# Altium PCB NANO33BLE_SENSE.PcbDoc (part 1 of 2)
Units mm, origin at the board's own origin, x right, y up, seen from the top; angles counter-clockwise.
Board outline 43.18 x 17.78 mm, 4 copper layers (TOP, GND, SIG, BOTTOM), stack 1.586 mm thick; 73 components, 66 nets, 343 pads, 193 vias.
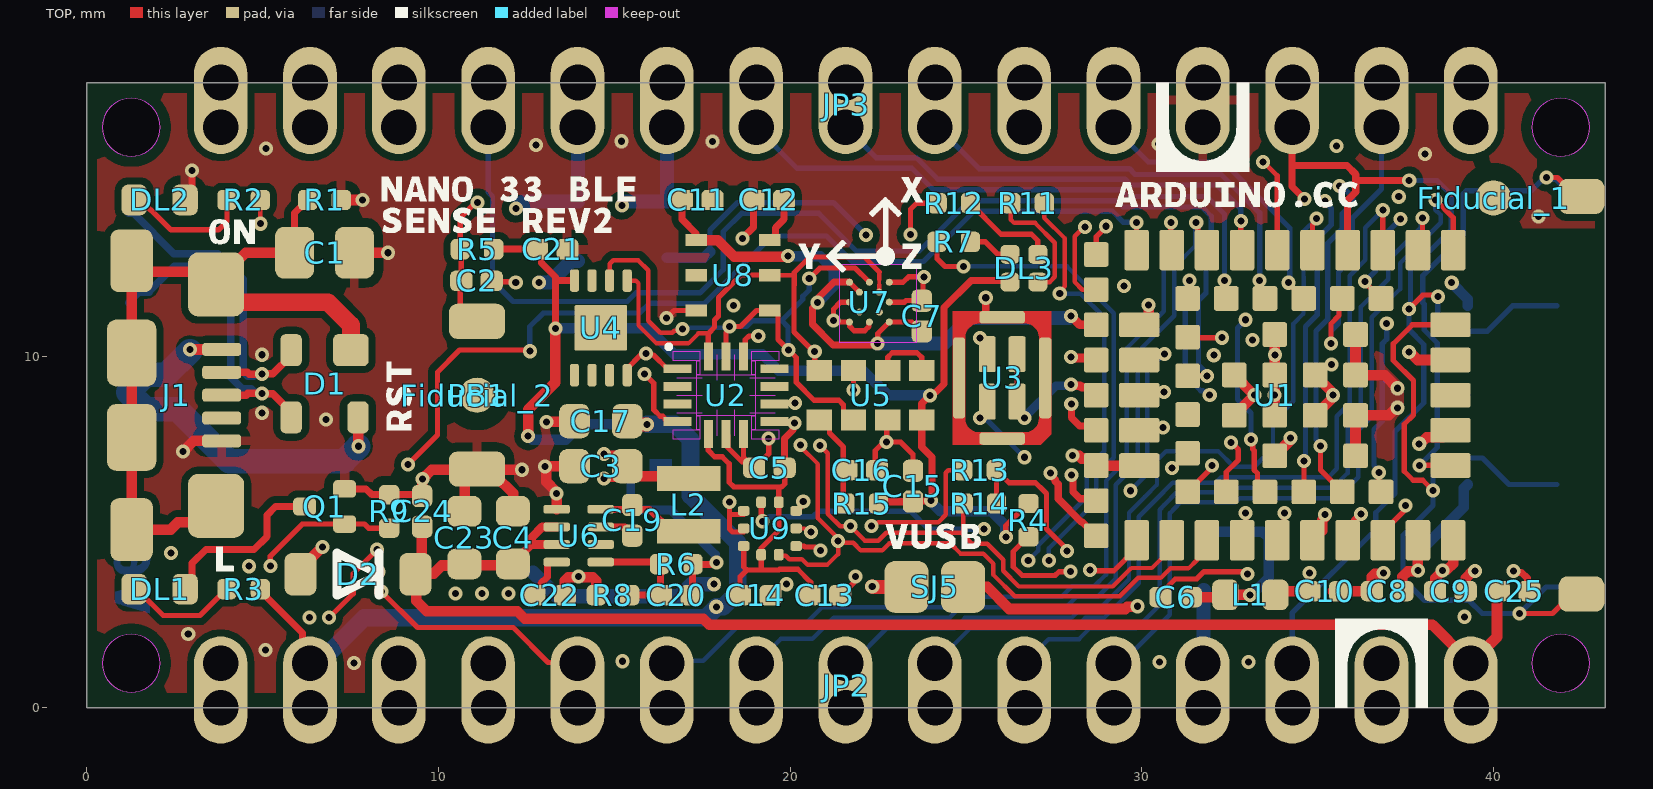
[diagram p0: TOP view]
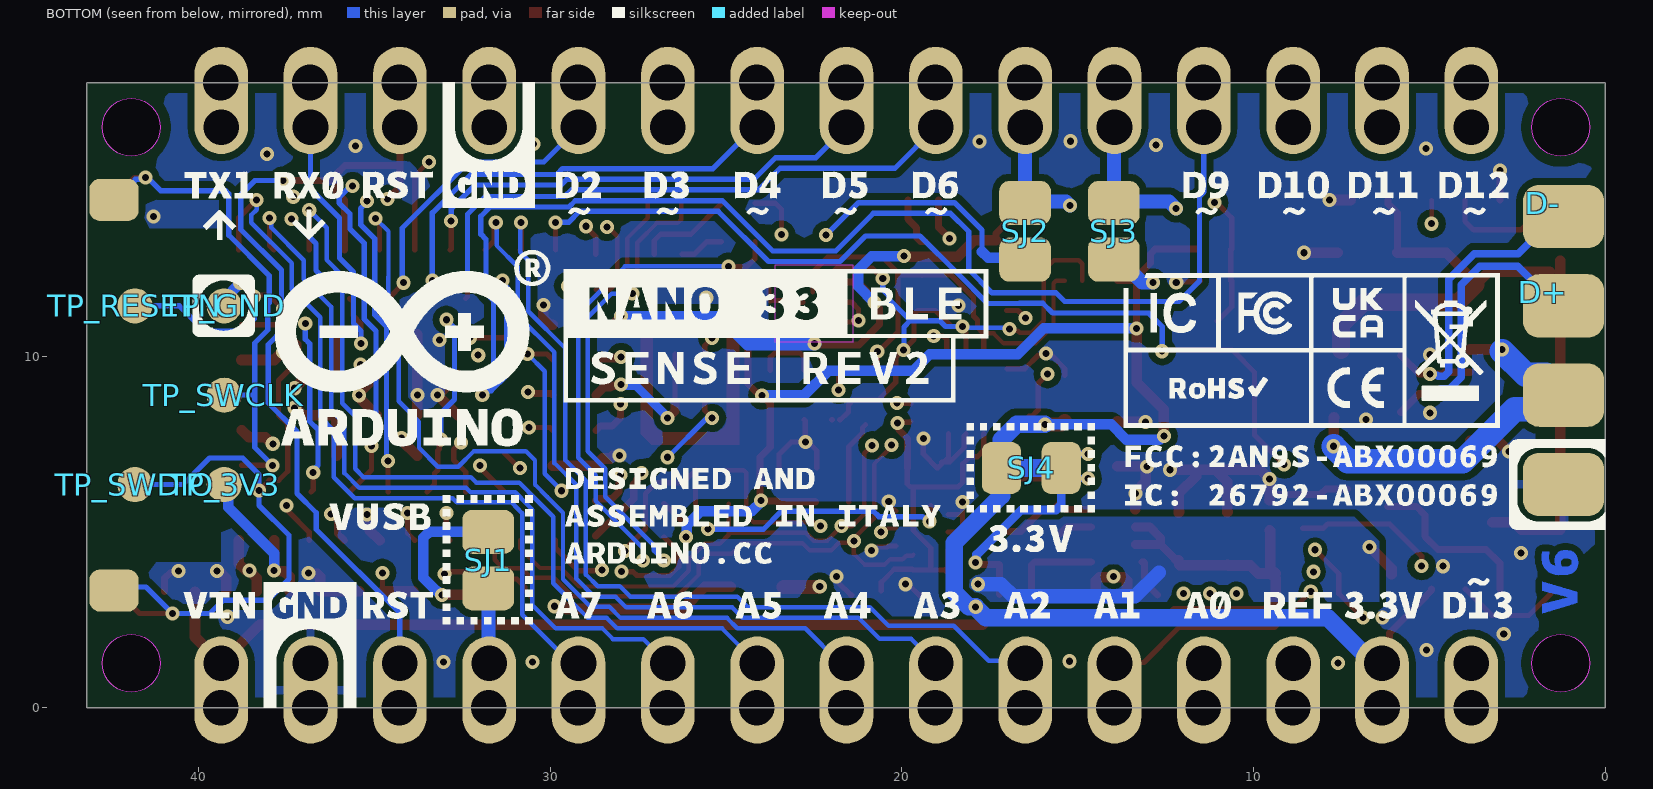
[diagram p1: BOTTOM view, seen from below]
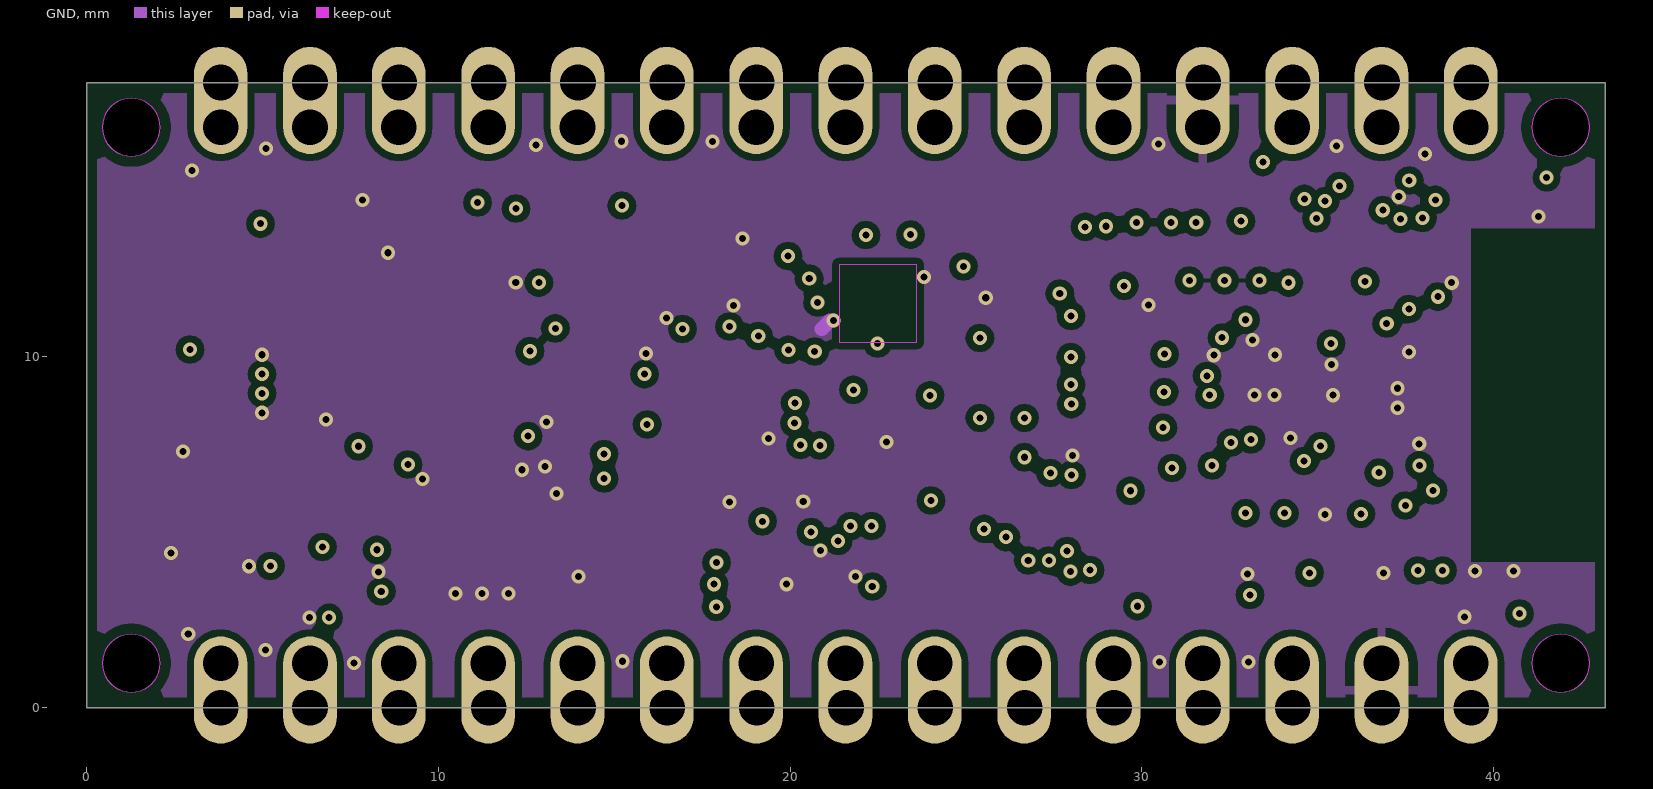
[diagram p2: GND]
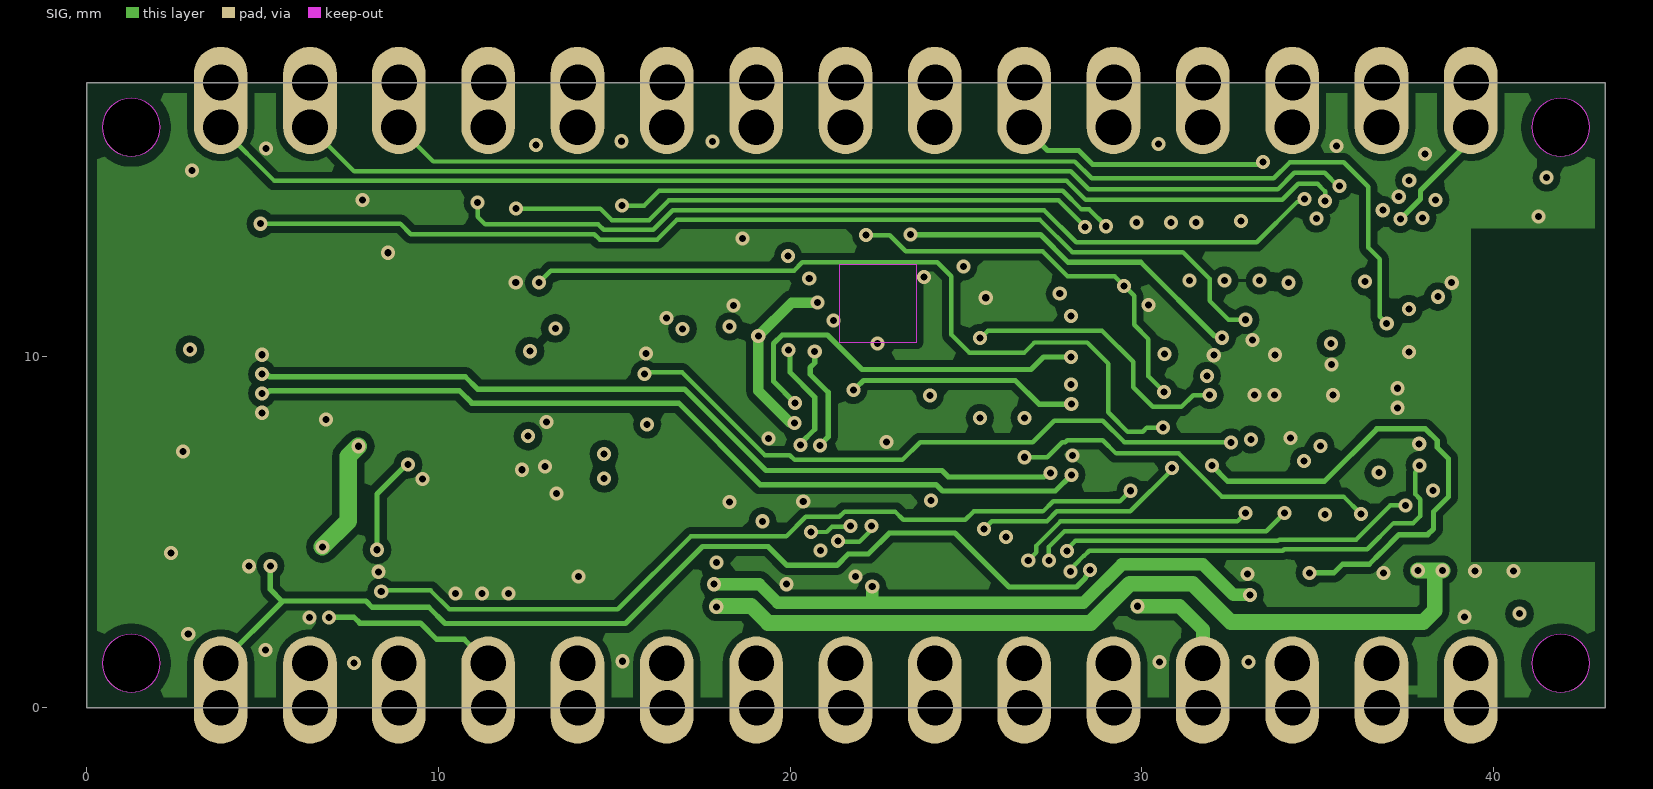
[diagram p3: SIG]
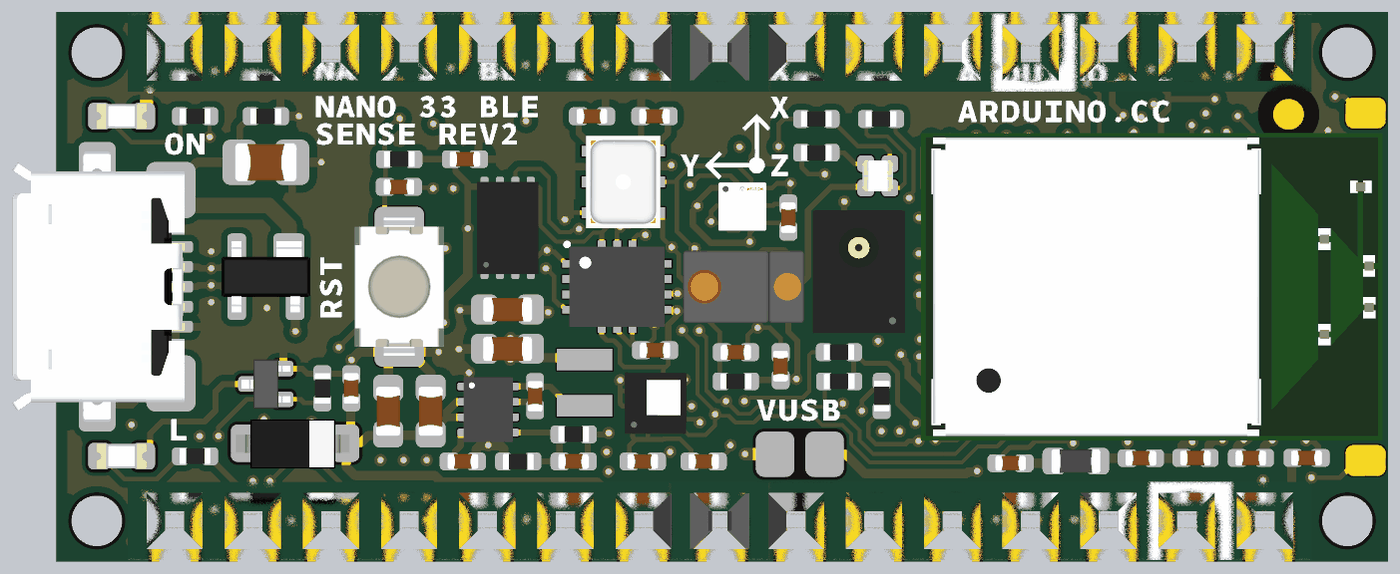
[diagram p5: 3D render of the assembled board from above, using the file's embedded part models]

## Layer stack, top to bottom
Top Solder: solder mask 0.0102, Solder Resist, Dk 3.5
TOP: signal copper 0.018
Dielectric 1: prepreg 0.14, PP-014, Dk 4.2
GND: signal copper 0.035
Dielectric2: core 1.2, FR-4, Dk 4.8
SIG: signal copper 0.035
Dielectric3: prepreg 0.14, PP-014, Dk 4.2
BOTTOM: signal copper 0.018
Bottom Solder: solder mask 0.0102, Solder Resist, Dk 3.5

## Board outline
43.18,0 0,0 0,17.78 43.18,17.78
cut-out: 1.27,0.445 ccw(c1.27,1.27) 2.095,1.27 ccw(c1.27,1.27) 1.27,2.095 ccw(c1.27,1.27) 0.445,1.27 ccw(c1.27,1.27)
cut-out: 1.27,15.684 ccw(c1.27,16.51) 2.095,16.51 ccw(c1.27,16.51) 1.27,17.335 ccw(c1.27,16.51) 0.445,16.51 ccw(c1.27,16.51)
cut-out: 41.91,15.684 ccw(c41.91,16.51) 42.735,16.51 ccw(c41.91,16.51) 41.91,17.335 ccw(c41.91,16.51) 41.084,16.51 ccw(c41.91,16.51)
cut-out: 41.91,0.445 ccw(c41.91,1.27) 42.735,1.27 ccw(c41.91,1.27) 41.91,2.095 ccw(c41.91,1.27) 41.084,1.27 ccw(c41.91,1.27)

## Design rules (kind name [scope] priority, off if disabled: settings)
BoardOutlineClearance USBbottomPADS [(ObjectKind = 'Pad') And (Component = 'Free') And (AsMM(PadXSize_AllLayers) = 2.3) And (AsMM(PadYSize_AllLayers) = 1.8)] p1: gap=0 ignorepadtopadclearanceinfootprint=FALSE
BoardOutlineClearance swdio_swclk [(ObjectKind = 'Pad') And (Name = 'Free-JTAG_PAD')] p2: gap=0 ignorepadtopadclearanceinfootprint=FALSE
BoardOutlineClearance Silk [(OnLayer('Top Overlay') OR OnLayer('Bottom Overlay'))] p3: gap=0 ignorepadtopadclearanceinfootprint=FALSE
BoardOutlineClearance MountingHoles [(ObjectKind = 'Pad') And (Name = 'Free-MH')] p4: gap=0 ignorepadtopadclearanceinfootprint=FALSE
BoardOutlineClearance Header_Castellated [((ObjectKind = 'Pad') And (Component = 'JP2')) OR                                                                                    ((ObjectKind = 'Pad') And (Component = 'JP3'))] p5: gap=0 ignorepadtopadclearanceinfootprint=FALSE
BoardOutlineClearance [All] p6: gap=0.3 ignorepadtopadclearanceinfootprint=FALSE
Clearance BGAclearance [WithinRoom('BGAfanout')] p1: gap=0.108 ignorepadtopadclearanceinfootprint=TRUE
Clearance GND_POLYGONS [(InNamedPolygon('GND_TOP') OR InNamedPolygon('GND_2') OR InNamedPolygon('GND_3') OR InNamedPolygon('GND_BOT'))] p2: gap=0.2 ignorepadtopadclearanceinfootprint=FALSE
Clearance "Generic clearance 0.15mm" [All] p3: gap=0.15 ignorepadtopadclearanceinfootprint=FALSE
ComponentClearance [All] p1: gap=0 collisioncheckmode=3 verticalgap=0 showdistances=FALSE
DiffPairsRouting [InDifferentialPairClass('USB')] p1: maxlimit=0.254 minlimit=0.15 mostfreqgap=0.254 toplayer_maxgap=0.15 toplayer_prefgap=0.15 toplayer_minwidth=0.21 toplayer_maxwidth=0.21 toplayer_prefwidth=0.21 midlayer14_mingap=0.25 midlayer14_maxgap=0.25 midlayer14_prefgap=0.25 midlayer14_minwidth=0.15 midlayer14_maxwidth=0.15 midlayer14_prefwidth=0.15 bottomlayer_maxgap=0.15 bottomlayer_prefgap=0.15 bottomlayer_minwidth=0.21 bottomlayer_maxwidth=0.21 bottomlayer_prefwidth=0.21 impedanceprofiledriven=TRUE impedanceprofileid={9B09AC36-4A16-4C97-8BAC-77357264EF75} impedanceprofilevalue=90.000000 maxuncoupledlength=12.7
HoleSize [All] p1: absolutevalues=TRUE maxlimit=6 minlimit=0.2 maxpercent=80.000 minpercent=20.000
HoleToHoleClearance [All] p1: gap=0.25 allowstackedmicrovias=TRUE
MinimumAnnularRing [All] p1: minimumring=0.1
MinimumSolderMaskSliver MinimumSolderMaskSliver_1 [(ObjectKind = 'Pad') And (Component = 'Fiducial_1') And (Name = 'Fiducial_1-1')] p1: minsoldermaskwidth=-1
MinimumSolderMaskSliver [All] p2: minsoldermaskwidth=0.147
NetAntennae Inductor [(ObjectKind = 'Component') And (Comment = 'MAKK2016T3R3M')] p1: netantennaetolerance=10
NetAntennae [All] p2: netantennaetolerance=0
PolygonConnect [All] p1: thpad.connectstyle=Relief thpad.reliefconductorwidth=0.254 thpad.reliefentries=4 thpad.polygonreliefangle="90 Angle" thpad.airgapwidth=0.254 smdpad.connectstyle=Relief smdpad.reliefconductorwidth=0.254 smdpad.reliefentries=4 smdpad.polygonreliefangle="90 Angle" smdpad.airgapwidth=0.254 via.connectstyle=Direct via.reliefconductorwidth=0.254 via.reliefentries=4 via.polygonreliefangle="90 Angle" via.airgapwidth=0.254
RoomDefinition BGAfanout [False vs False] p1: confinementstyle=ConfineIn formatcopy=TRUE lockcomponents=FALSE outline 22.16,12.23 22.925,12.23 22.925,11.702 22.16,11.702
RoomDefinition NANO33BLE_SENSE [InComponentClass('NANO33BLE_SENSE')] p2: confinementstyle=ConfineIn formatcopy=TRUE lockcomponents=FALSE outline 0,0 43.18,0 43.18,17.78 0,17.78
RoutingVias [All] p1: holewidth=0.2 width=0.4 viastyle="Through Hole" minholewidth=0.2 minwidth=0.4 maxholewidth=0.2 maxwidth=0.4
ShortCircuit SJ4 [Component = 'SJ4' vs (InNet('+3V3') OR InNet('NetC3_2'))] p1: allowed=TRUE
ShortCircuit [All] p2: allowed=FALSE
SilkToSilkClearance [All] p1: silktosilkclearance=0.2
SilkToSolderMaskClearance [IsPad] p1: minsilkscreentomaskgap=0 clearancetoexposedcopper=TRUE
SolderMaskExpansion Solder_VIA [IsVia] p1: expansion=0.102 istentingtop=TRUE
SolderMaskExpansion [All] p2: expansion=0.102 istentingtop=FALSE
UnRoutedNet [All] p1: checkbadconnections=TRUE
Width BGAwidth [WithinRoom('BGAfanout')] p1: maxlimit=3 minlimit=0.108 preferedwidth=0.15 midlayer1_minwidth=0.127 midlayer14_minwidth=0.127 bottomlayer_minwidth=0.127 minimp=50.000000 maximp=50.000000 favimp=50.000000
Width [All] p2: maxlimit=5 minlimit=0.127 preferedwidth=0.2 minimp=50.000000 maximp=50.000000 favimp=50.000000
20 further rules are at their usual default settings.

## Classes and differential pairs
differential pair class USB: USB
pad class SMDPaste_OFF: FD1-P$1 J3-4
differential pair USB: +USB_P -USB_N

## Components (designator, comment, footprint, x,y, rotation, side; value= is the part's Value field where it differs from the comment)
C1 "C0805C472KDRACTU" CAP-0805 6.765,12.94 r180 top value=4.7nF
C2 "GRM155R61H104KE19D" CAP-0402 11.085,12.14 r0 top value=100nF
C3 "GRM188R61E106MA73J" CAP-0603 14.62,6.87 r0 top value=10µF
C4 "GRM188R61E106MA73J" CAP-0603 12.12,4.84 r270 top value=10µF
C5 "C0402C104K4RACTU" CAP-0402 19.412,6.825 r180 top value=100nF
C6 "C0402C100K5RACTU" CAP-0402 30.965,3.148 r180 top value=1nF
C7 "GRM155R61H104KE19D" CAP-0402 23.745,11.14 r270 top value=100nF
C8 "GRM155R61H104KE19D" CAP-0402 36.975,3.32 r0 top value=100nF
C9 "GRM155R61H104KE19D" CAP-0402 38.775,3.32 r0 top value=100nF
C10 "C0402C100K5RACTU" CAP-0402 35.2,3.312 r0 top value=1nF
C11 "GRM155R61H104KE19D" CAP-0402 17.362,14.44 r0 top value=100nF
C12 "GRM155R61H104KE19D" CAP-0402 19.392,14.44 r180 top value=100nF
C13 "C0402C103K5RACTU" CAP-0402 20.991,3.205 r0 top value=10nF
C14 "GRM155R60J475ME47D" CAP-0402 19.012,3.205 r0 top value=4.7µF
C15 "C0402C105K8PACTU" CAP-0402 23.494,6.305 r270 top value=1µF
C16 "C0402C105K8PACTU" CAP-0402 22.038,6.76 r180 top value=1µF
C17 "GRM188R61E106MA73J" CAP-0603 14.62,8.15 r0 top value=10µF
C19 "GRM155R61H104KE19D" CAP-0402 15.515,5.33 r270 top value=100nF
C20 "C0402C220J5GAC7411" CAP-0402 16.765,3.205 r0 top value=22pF
C21 "GRM155R61H104KE19D" CAP-0402 13.235,13.04 r180 top value=100nF
C22 "C0402C105K8PACTU" CAP-0402 13.165,3.205 r180 top value=1µF
C23 "GRM188R61E106MA73J" CAP-0603 10.74,4.84 r270 top value=10µF
C24 "GRM155R61H104KE19D" CAP-0402 9.54,5.585 r90 top value=100nF
C25 "C0402C105K8PACTU" CAP-0402 40.585,3.32 r180 top value=1µF
D1 "PRTR5V0U2X,215" SOT190P230X110-4N 6.765,9.215 r180 top
D2 "PMEG6020AELRX" SOD123-1 7.715,3.8 r180 top
D+ "CMP-018-0005-A.3" TP-1.00MM#1 1.778,11.811 r0 top
D- "CMP-018-0005-A.3" TP-1.00MM#1 1.778,14.351 r0 top
DL1 "KPT-1608YC" LEDC1608X80N-AK 2.075,3.375 r180 top
DL2 "HSMG-C190" LEDC1608X80N-AK 2.075,14.44 r180 top
DL3 "SMLP34RGB2W3" SMLP34RGB2W 26.65,12.5 r0 top
Fiducial_1 "Fiducial mark 1mm with 2mm solder" "Fiducial mark 1mm with circle-Footprint-1" 40,14.5 r90 top
Fiducial_2 "Fiducial mark 1mm with 2mm solder" "Fiducial mark 1mm with circle-Footprint-1" 11.1,8.89 r90 top
J1 "ZX62-AB-5PA(31)" ZX62-AB-5PA 1.28,8.89 r270 top
JP2 "PINHD-1X15-NANO-ANALOG-CASTELLATED" PINHD-1X14_5VF#1 3.81,1.27 r180 top locked
JP3 "PINHD-1X15-NANO-DIGITAL" PINHD-1X14_5VF#2 39.37,16.51 r0 top locked
L1 "BLM18EG101TN1D" L-0603 33.088,3.213 r0 top
L2 "MAKK2016T3R3M" MAKK2016T3R3M-Footprint-1 17.12,5.77 r90 top value=3.3µH
PB1 "IT-1185AP1C-160G-GTR" C&K_PTS820_NO_HOLES-1 11.1,8.89 r90 top
Q1 "2N7002T-7-F" SOT523 6.765,5.725 r90 top
R1 "CRCW04021M00FKED" RES-0402 6.765,14.44 r180 top value=1M
R2 "CRCW0402330RJNED" RES-0402 4.465,14.44 r0 top value=330
R3 "CRCW0402330RJNED" RES-0402 4.465,3.375 r0 top value=330
R4 "RC0402FR-074K7L" RES-0402 26.779,5.335 r90 top value=4.7k
R5 "RC0402FR-074K7L" RES-0402 11.1,13.04 r0 top value=4.7k
R6 "CRCW0402976KFKED" RES-0402 16.765,4.085 r0 top value=976k
R7 "CRCW04021K00FKEDC" RES-0402 24.655,13.25 r0 top value=1k
R8 "CRCW0402220KFKED" RES-0402 14.965,3.205 r0 top value=220k
R9 "CRCW0402976KFKED" RES-0402 8.6,5.585 r270 top value=976k
R11 "CRCW04021K00FKEDC" RES-0402 26.755,14.35 r180 top value=1k
R12 "CRCW04021K00FKEDC" RES-0402 24.655,14.35 r0 top value=1k
R13 "RC0402FR-074K7L" RES-0402 25.388,6.76 r0 top value=4.7k
R14 "RC0402FR-074K7L" RES-0402 25.395,5.81 r0 top value=4.7k
R15 "RC0402FR-0722RL" RES-0402 22.038,5.81 r0 top value=22
SJ1 "SMD solder JUMPER 0805" SJ#1 31.762,4.2 r270 bottom
SJ2 "SMD solder JUMPER 0805" SJ#1 16.5,13.55 r90 bottom
SJ3 "SMD solder JUMPER 0805" SJ#1 13.975,13.55 r90 bottom
SJ4 "SMD solder JUMPER CLOSED" SJ#2 16.32,6.82 r0 bottom
SJ5 "SMD solder JUMPER 0805" SJ#1 24.115,3.439 r0 top
TP_3V3 "CMP-018-0005-A.3" TP-1.00MM#2 39.268,6.35 r90 bottom
TP_GND "CMP-018-0005-A.3" TP-1.00MM#2 39.268,11.43 r90 bottom
TP_RESETN "CMP-018-0005-A.3" TP-1.00MM#2 41.808,11.43 r90 bottom
TP_SWCLK "CMP-018-0005-A.3" TP-1.00MM#2 39.268,8.89 r90 bottom
TP_SWDIO "CMP-018-0005-A.3" TP-1.00MM#2 41.808,6.35 r90 bottom
U1 "NINA-B306" NINA-B3X 35.552,8.89 r0 top locked
U2 "BMI270" VFLGA14 18.177,8.89 r0 top locked
U3 "MP34DT06JTR" HCLGA 26.03,9.381 r90 top locked
U4 "ATECC608A-MAHDA-T" UDFN8 14.62,10.805 r0 top
U5 "APDS-9660" APDS-9660-Footprint-1 22.289,8.89 r0 top locked
U6 "MP2322GQH" QFN50P150X200X90-8L 13.99,4.895 r0 top
U7 "BMM150" FP-BMM150-MFG 22.289,11.5 r0 top
U8 "HS3003" HS3003-Footprint-1 18.377,12.3 r90 top
U9 "LPS22HBTR" LPS22H 19.427,5.1 r0 top

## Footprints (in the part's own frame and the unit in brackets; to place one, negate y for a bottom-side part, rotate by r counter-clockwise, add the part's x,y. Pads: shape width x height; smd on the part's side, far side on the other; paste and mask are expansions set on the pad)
APDS-9660-Footprint-1 [mm]
  rect 0.72x0.6 smd mask+0.05: 1(-1.455,0.7) 2(-0.485,0.7) 3(0.485,0.7) 4(1.455,0.7) 5(1.455,-0.7) 6(0.485,-0.7) 7(-0.485,-0.7) 8(-1.455,-0.7)
  body extent -1.97,-1.18 1.97,1.18, height 1.3
C&K_PTS820_NO_HOLES-1 [mm]
  rrect49% 1x1.6 smd mask+0.05: 1(-2.1,0) 2(2.1,0)
  body extent -2.25,-1.45 2.25,1.45, height 2
CAP-0402 [mm] "Chip Capacitor, 2-Leads, Body  0402 (in) 1005 (mm), IPC Medium Density"
  rrect52% 0.63x0.58 smd mask+0: 1(-0.435,0) 2(0.435,0)
  body extent -0.5,-0.25 0.5,0.25, height 0.5
CAP-0603 [mm] "Chip Capacitor, Body 0603 imperial,1.6x0.8mm, IPC High Density"
  rrect51% 0.87x0.97 smd mask+0: 1(-0.75,0) 2(0.75,0)
  body extent -0.8,-0.4 0.8,0.4, height 0.8
CAP-0805 [mm] "Chip Capacitor, Body 0805 imperial, 2.0x1.2mm, IPC Medium Density"
  rrect45% 1.11x1.47 smd mask+0: 1(-0.85,0) 2(0.85,0)
  body extent -1,-0.62 1,0.63, height 1.25
"Fiducial mark 1mm with circle-Footprint-1" [mm]
  round 1 smd paste-10 mask+0.5: 1(0,0)
  TOP pour cut-out: 0,1 0.383,0.924 0.707,0.707 0.924,0.383 1,0 1,0 0.924,-0.383 0.707,-0.707 0.383,-0.924 0,-1 0,-1 -0.383,-0.924 -0.707,-0.707 -0.924,-0.383 -1,0 -1,0 -0.924,0.383 -0.707,0.707 -0.383,0.924 0,1
FP-BMM150-MFG [mm]
  round 0.2 smd mask+0.02: A1(-0.601,0.601) A3(-0.035,0.601) A5(0.531,0.601) B2(-0.318,0.318) B4(0.248,0.318) C1(-0.601,0.035) C5(0.531,0.035) D2(-0.318,-0.248) D4(0.248,-0.248) E1(-0.601,-0.531) E3(-0.035,-0.531) E5(0.531,-0.531)
  body extent -1.3,-1.3 1.3,1.3, height 0.25
HCLGA [mm]
  rrect22% 1.02x0.48 smd paste+0 mask+0: 1(-0.675,-0.425) 2(0.675,-0.425) 3(0.675,0.425) 4(-0.675,0.425)
  rrect50% 0.35x1.3 smd paste+0 mask+0: 5(-1.725,0) 5(1.725,0)
  rrect50% 2.3x0.35 smd paste+0 mask+0: 5(0,1.225) 5(0,-1.225)
  TOP region: 1.9,0 1.9,1.4 -1.9,1.4 -1.9,-1.1 -1.6,-1.4 1.9,-1.4 1.9,0 1.55,0 1.55,-0.65 1.52,-0.803 1.433,-0.933 1.303,-1.02 1.15,-1.05 1.15,-1.05 -1.15,-1.05 -1.303,-1.02 -1.433,-0.933 -1.52,-0.803 -1.55,-0.65 -1.55,-0.65 -1.55,0.65 -1.52,0.803 -1.433,0.933 -1.303,1.02 -1.15,1.05 -1.15,1.05 1.15,1.05 1.303,1.02 1.433,0.933 1.52,0.803 1.55,0.65 1.55,0.65 1.55,0
  body extent -2,-1.5 2,1.5, height 1
HS3003-Footprint-1 [mm]
  rect 0.35x0.61 smd mask+0.05: 1(-1,-1.05) 2(0,-1.05) 3(1,-1.05) 4(1,1.05) 5(0,1.05) 6(-1,1.05)
  body extent -1.5,-1.2 1.5,1.2, height 0.9
L-0603 [mm] "Chip Inductor - Body 0603 imperial,1.6x0.8mm, IPC High Density"
  rrect51% 0.75x0.87 smd mask+0: 1(-0.71,0) 2(0.71,0)
  body extent -0.8,-0.4 0.8,0.4, height 0.8
LEDC1608X80N-AK [mm]
  rrect50% 0.72x0.87 smd: A(0.725,0) C(-0.725,0)
  body extent -0.8,-0.4 0.8,0.4, height 0.79
LPS22H [mm]
  rrect50% 0.28x0.33 smd mask+0.02: 1(-0.25,-0.745) 2(0.25,-0.745) 6(0.25,0.745) 7(-0.25,0.745)
  rrect50% 0.33x0.28 smd mask+0.02: 3(0.745,-0.5) 4(0.745,0) 5(0.745,0.5) 8(-0.745,0.5) 9(-0.745,0) 10(-0.745,-0.5)
  body extent -1,-1 1,1, height 0.8
MAKK2016T3R3M-Footprint-1 [mm]
  rect 0.7x1.8 smd mask+0.05: 1(-0.75,0) 2(0.75,0)
  body extent -1,-0.8 1,0.8, height 1
NINA-B3X [mm]
  rrect18% 0.7x1.15 smd paste+0 mask+0: 1(-5.7,-4.125) 2(-4.7,-4.125) 3(-3.7,-4.125) 4(-2.7,-4.125) 5(-1.7,-4.125) 6(-0.7,-4.125) 7(0.3,-4.125) 8(1.3,-4.125) 9(2.3,-4.125) 10(3.3,-4.125) 16(3.3,4.125) 17(2.3,4.125) 18(1.3,4.125) 19(0.3,4.125) 20(-0.7,4.125) 21(-1.7,4.125) 22(-2.7,4.125) 23(-3.7,4.125) 24(-4.7,4.125) 25(-5.7,4.125)
  rrect18% 1.15x0.7 smd paste+0 mask+0: 11(3.225,-2) 12(3.225,-1) 13(3.225,0) 14(3.225,1) 15(3.225,2) 26(-5.625,2) 27(-5.625,1) 28(-5.625,0) 29(-5.625,-1) 30(-5.625,-2)
  rrect18% 0.7x0.7 smd paste+0 mask+0: 31(-4.25,-2.75) 32(-3.15,-2.75) 33(-2.05,-2.75) 34(-0.95,-2.75) 35(0.15,-2.75) 36(1.25,-2.75) 37(1.25,2.75) 38(0.15,2.75) 39(-0.95,2.75) 40(-2.05,2.75) 41(-3.15,2.75) 42(-4.25,2.75) 43(-4.25,1.65) 44(-4.25,0.55) 45(-4.25,-0.55) 46(-4.25,-1.65) 47(-6.85,4) 48(-6.85,3) 49(-6.85,2) 50(-6.85,1) 51(-6.85,0) 52(-6.85,-1) 53(-6.85,-2) 54(-6.85,-3) 55(-6.85,-4) GND1(0.525,-1.725) GND2(0.525,-0.575) GND3(0.525,0.575) GND4(0.525,1.725) GND5(-0.625,-0.575) GND6(-0.625,0.575) GND7(-1.775,-1.725) GND8(-1.775,-0.575) GND9(-1.775,0.575) GND10(-1.775,1.725) GND11(-2.925,-0.575) GND12(-2.925,0.575)
  body extent -7.5,-5 7.5,5, height 2.27
PINHD-1X14_5VF#1 [mil]
  round 27.56 hole 40 mask+7.87: 1(0,50) 2(-100,50) 3(-200,50) 4(-300,50) 5(-400,50) 6(-500,50) 7(-600,50) 8(-700,50) 9(-800,50) 10(-900,50) 11(-1000,50) 12(-1100,50) 13(-1200,50) 14(-1300,50) 15(-1400,50)
  oval 60x120 hole 40 copper offset 0,30 paste-100: 1(0,0) 2(-100,0) 3(-199.41,0) 4(-299.41,0) 5(-399.41,0) 6(-499.41,0) 7(-599.41,0) 8(-699.41,0) 9(-799.41,0) 10(-899.41,0) 11(-999.41,0) 12(-1099.41,0) 13(-1199.41,0) 14(-1299.41,0) 15(-1399.41,0)
  body extent -1454,-50 60,50, height 335
PINHD-1X14_5VF#2 [mil]
  oval 60x120 hole 40 copper offset 0,30 paste-100: 1(-0.59,0) 2(-100.59,0) 3(-200.59,0) 4(-300.59,0) 5(-400.59,0) 6(-500.59,0) 7(-600.59,0) 8(-700.59,0) 9(-800.59,0) 10(-900.59,0) 11(-1000.59,0) 12(-1100.59,0) 13(-1200.59,0) 14(-1300,0) 15(-1400,0)
  round 27.56 hole 40 mask+7.87: 1(0,50) 2(-100,50) 3(-200,50) 4(-300,50) 5(-400,50) 6(-500,50) 7(-600,50) 8(-700,50) 9(-800,50) 10(-900,50) 11(-1000,50) 12(-1100,50) 13(-1200,50) 14(-1300,50) 15(-1400,50)
  body extent -1460,-50 54,50, height 335
QFN50P150X200X90-8L [mm] "QFN, 8-Leads, Body 1,50x2,00mm, Pitch 0,50mm, IPC High Density"
  rrect50% 0.75x0.25 smd mask+0.05: 1(-0.625,0.75) 2(-0.625,0.25) 3(-0.625,-0.25) 4(-0.625,-0.75) 5(0.625,-0.75) 6(0.625,-0.25) 7(0.625,0.25) 8(0.625,0.75)
  body extent -0.8,-1.05 0.8,1.05, height 0.9
RES-0402 [mm] "Chip Resistor, 2-Leads, Body  0402 (in) 1005 (mm), IPC Medium Density"
  rrect51% 0.55x0.58 smd mask+0: 1(-0.475,0) 2(0.475,0)
  body extent -0.5,-0.25 0.5,0.25, height 0.34
SJ#1 [mm]
  rrect45% 1.25x1.47 smd: 1(-0.805,0) 2(0.805,0)
SJ#2 [mm]
  rrect45% 1.11x1.47 smd mask+0: 1(-0.85,0) 2(0.85,0)
  TOP region: -0.31,0.254 -0.31,-0.254 0.31,-0.254 0.31,0.254
SMLP34RGB2W [mm]
  rrect52% 0.54x0.54 smd mask+0.05: 1(-0.395,-0.395) 2(-0.395,0.395) 3(0.395,0.395) 4(0.395,-0.395)
  body extent -0.5,-0.5 0.5,0.5, height 0.2
SOD123-1 [mm]
  rrect50% 0.91x1.22 smd: A(1.635,0) C(-1.635,0)
  silkscreen extent -0.6,-0.6 0.6,0.6, body extent -1.78,-0.78 1.92,0.82, height 1.27
SOT190P230X110-4N [mm]
  rrect33% 1.01x0.91 smd paste+0 mask+0: 1(-0.75,-0.955)
  rrect49% 0.61x0.91 smd paste+0 mask+0: 2(0.95,-0.955) 3(0.95,0.955) 4(-0.95,0.955)
  body extent -1.45,-1.15 1.45,1.15, height 1
SOT523 [mm]
  rrect50% 0.5x0.66 smd: D(0,0.57) G(-0.5,-0.57) S(0.5,-0.57)
  body extent -0.8,-0.8 0.8,0.8, height 0.8
TP-1.00MM#1 [mm]
  round 1 smd far side paste-2.54 mask+0: X(0,0)
TP-1.00MM#2 [mm]
  rrect100% 1x1 smd paste-2.54: X(0,0)
UDFN8 [mm] "QFN, 8-Leads, Body 3.00x2.00mm, Pitch 0.50mm, Thermal Pad 1.30x1.50mm, IPC Medium Density"
  rrect54% 0.26x0.64 smd paste+0 mask+0: 1(-0.75,-1.345) 2(-0.25,-1.345) 3(0.25,-1.345) 4(0.75,-1.345) 5(0.75,1.345) 6(0.25,1.345) 7(-0.25,1.345) 8(-0.75,1.345)
  rrect8% 1.5x1.3 smd paste-1.5 mask+0: 9(0,0)
  body extent -1,-1.5 1,1.5, height 0.55
VFLGA14 [mm]
  rect 0.8x0.25 smd mask+0.05: 1(-1.375,0.75) 2(-1.375,0.25) 3(-1.375,-0.25) 4(-1.375,-0.75) 8(1.375,-0.75) 9(1.375,-0.25) 10(1.375,0.25) 11(1.375,0.75)
  rect 0.25x0.8 smd mask+0.05: 5(-0.5,-1.1) 6(0,-1.1) 7(0.5,-1.1) 12(0.5,1.1) 13(0,1.1) 14(-0.5,1.1)
  TOP keep-out region: -0.83,-0.98 -0.83,-0.58 -0.74,-0.58 -0.74,-0.98
  TOP keep-out region: 0.74,-0.98 0.74,-0.58 0.83,-0.58 0.83,-0.98
  TOP keep-out region: 0.74,0.58 0.74,0.98 0.83,0.98 0.83,0.58
  TOP keep-out region: -0.83,0.58 -0.83,0.98 -0.74,0.98 -0.74,0.58
  TOP keep-out region: -1.5,-1.25 -1.5,-0.98 -0.74,-0.98 -0.74,-1.25
  TOP keep-out region: 0.74,-1.25 0.74,-0.98 1.5,-0.98 1.5,-1.25
  TOP keep-out region: 0.74,0.98 0.74,1.25 1.5,1.25 1.5,0.98
  TOP keep-out region: -1.5,0.98 -1.5,1.25 -0.74,1.25 -0.74,0.98
  TOP keep-out region: -0.83,-0.58 -0.83,0.58 0.83,0.58 0.83,-0.58
  TOP keep-out lines w0.01: -1.4,-0.5 -0.67,-0.5 ; -1.4,0 -0.67,0 ; -1.4,0.5 -0.67,0.5 ; -0.25,-1.15 -0.25,-0.42 ; -0.25,0.42 -0.25,1.15 ; 0.25,-1.15 0.25,-0.42 ; 0.25,0.42 0.25,1.15 ; 0.67,-0.5 1.4,-0.5 ; 0.67,0 1.4,0 ; 0.67,0.5 1.4,0.5
  silkscreen extent -1.67,1.32 -1.58,1.42, body extent -1.55,-1.3 1.55,1.3, height 0.86
ZX62-AB-5PA [mm]
  rrect49% 0.37x1.11 smd paste+0 mask+0: 1(-1.3,2.56) 2(-0.65,2.56) 3(0,2.56) 4(0.65,2.56) 5(1.3,2.56)
  rrect37% 1.825x1.6 smd paste+0 mask+0: M1(-3.147,2.4) M4(3.147,2.4)
  rrect37% 1.78x1.2 smd paste+0 mask+0: M2(-3.82,0) M3(3.82,0)
  rrect37% 1.9x1.4 smd paste+0 mask+0: M5(-1.2,0) M6(1.2,0)
  body extent -4.4,-2.75 4.4,2.85, height 2.75

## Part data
C1: library part C0059-A.11, "CAP CHIP 0805 4.7nF 1000V X7R 10%", Case Code (Imperial)=0805, Case Code (Metric)=2012, Dielectric=X7R, Manufacturer=KEMET, Tolerance=10%, Voltage=1kV
C2 C7 C8 C9 C11 C12 C19 C21 C24: library part C0015-A.11, "CAP CHIP 0402 100nF 50V X5R 10%", Case Code (Imperial)=0402, Case Code (Metric)=1005, Dielectric=X5R, Manufacturer=Murata, Tolerance=10%, Voltage=50V
C3 C4 C17 C23: library part C0047-A.15, "CAP CHIP 0603 10uF 25V X5R 20%", Case Code (Imperial)=0603, Case Code (Metric)=1608, Dielectric=X5R, Manufacturer=Murata, Tolerance=20%, Voltage=25V
C5: library part C0012-A.11, "CAP CHIP 0402 100nF 16V X7R 10%", Case Code (Imperial)=0402, Case Code (Metric)=1005, Dielectric=X7R, Manufacturer=KEMET, Manufacturer 2=AVX, Manufacturer Part Number 2=0402YC104KAT2A, Tolerance=10%, Voltage=16V
C6 C10: library part C0007-A.11, "CAP CHIP 0402 1nF 50V X7R 10%", Case Code (Imperial)=0402, Case Code (Metric)=1005, Dielectric=X7R, Manufacturer=KEMET, Manufacturer 2=Murata, Manufacturer Part Number 2=GRM155R71H102KA01D, Tolerance=10%, Voltage=50V
C13: library part C0009-A.11, "CAP CHIP 0402 10nF 50V X7R 10%", Case Code (Imperial)=0402, Case Code (Metric)=1005, Dielectric=X7R, Manufacturer=KEMET, Manufacturer 2=AVX, Manufacturer Part Number 2=4025C103KAT2A, Tolerance=10%, Voltage=50V
C14: library part C0037-A.11, "CAP CHIP 0402 4.7uF 6V3 X5R 20%", Case Code (Imperial)=0402, Case Code (Metric)=1005, Dielectric=X5R, Manufacturer=Murata, Tolerance=20%, Voltage=6.3V
C15 C16 C22 C25: library part C0017-A.11, "CAP CHIP 0402 1uF 10V X5R 10%", Case Code (Imperial)=0402, Case Code (Metric)=1005, Dielectric=X5R, Manufacturer=KEMET, Manufacturer 2=AVX, Manufacturer Part Number 2=GRM155R61A105KE15D, Tolerance=10%, Voltage=10V
C20: library part C0029-A.11, "CAP CHIP 0402 22pF 50V C0G 5%", Case Code (Imperial)=0402, Case Code (Metric)=1005, Dielectric=C0G, Manufacturer=KEMET, Manufacturer 2=AVX, Manufacturer Part Number 2=04025A220JAT2A, Tolerance=5%, Voltage=50V
D1: library part D0025-A.4, "TVS ARRAY 4LIN.8kV 1pF SOT143B", Manufacturer=Nexperia
D2: library part D0026-A.5, "DIODE SCHOTTKY SMD 2A 60V SOD123FL", Forward Current=2A, Forward Voltage=0.6V, Manucturer Part Number 2=SS26L, Manufacturer=Nexperia
D+ D- TP_3V3 TP_GND TP_RESETN TP_SWCLK TP_SWDIO: library part UT0013-A.4, "Test point 1.00mm"
DL1: library part L0008-A.4, "LED SMD 0603 GIA588   8mcd 120^", Manufacturer=Kingbright
DL2: library part L0009-A.4, "LED SMD 0603 GREEN/568 15mcd 120^", Manufacturer=Broadcom
DL3: library part L0014-A.9, "LED RGB DIFFUSED PICOLED SMD", Case Code (Imperial)=0404, Case Code (Metric)=1010, Color=Blue,Green,Red, Forward Current=20mA, Forward Voltage=3V, Lens Color=White, Manufacturer="ROHM Semiconductor", Max Operating Temperature=85°C, Min Operating Temperature=-40°C, Package Quantity=1, Test Current=5mA
Fiducial_1 Fiducial_2: library part UT0024-A.6
J1: library part J0039-A.6, "CONN USB MICRO F/90^ SMD TipoAB 5x1", Manufacturer=Hirose
JP2: library part J0158-A.2, "CONN THD SOCKET F/1/D 15V JANALOG NANO-TYPE CASTELLATED"
JP3: library part J0183-A.1, "CONN THD SOCKET F/1/D 15V JDIGITAL NANO-TYPE CASTELLATED"
L1: library part I0022-A.4, "FERRITE SMD 0603 45mOHM 2A", Case Code (Imperial)=0603, Case Code (Metric)=1608, Current=2A, DC Resistance (DCR)=45mR, Manufacturer=Murata, Max Operating Temperature=125°C, Min Operating Temperature=-55°C, Package Quantity=1, Test Frequency=100MHz, Tolerance=25%
L2: library part I0045-A.9, "IND CHIP 0806 3.3 uH 20% 1.2A", Case Code (Imperial)=0806, Case Code (Metric)=2016, Current Rating=1.2A, DC Resistance (DCR)=255mR, Inductance=3.3µH, Manufacturer="Taiyo Yuden", Manufacturer 2=Murata, Manufacturer Part Number 2=LQM2MPN3R3NG0L, Max DC Current=1.15A, Max Operating Temperature=105°C, Min Operating Temperature=-40°C, Package Quantity=3000, Resistor Type=Wirewound, Test Frequency=2MHz, Tolerance=20%
PB1: library part B0001-A.7, "PUSHBUTTON WHITE NO ANCHORS", Color=White, Manufacturer=Switronic
Q1: library part T0003-A.2, "MOSFET N-CH 60V 115mA SOT523", Manufacturer="Diodes Inc."
R1: library part R0058-A.11, "RES CHIP 0402 1M 1% 1/16W", Case Code (Imperial)=0402, Case Code (Metric)=1005, Manufacturer=Vishay, Manufacturer 2=Panasonic, Manufacturer Part Number 2=ERJ-2RKF1004X, Power=63mW, Tolerance=1%
R2 R3: library part R0017-A.11, "RES CHIP 0402 330R 5% 1/16W", Case Code (Imperial)=0402, Case Code (Metric)=1005, Manufacturer=Vishay, Manufacturer 2=Panasonic, Manufacturer Part Number 2=ERJ-2GEJ331X, Power=63mW, Tolerance=5%
R4 R5 R13 R14: library part R0013-A.11, "RES CHIP 0402 4K7 1% 1/16W", Case Code (Imperial)=0402, Case Code (Metric)=1005, Manufacturer=Yageo, Power=63mW, Tolerance=1%
R6 R9: library part R0070-A.12, "RES CHIP 0402 976K 1% 1/16W", Case Code (Imperial)=0402, Case Code (Metric)=1005, Manufacturer=Vishay, Manufacturer 2=Panasonic, Manufacturer Part Number 2=ERJ-2RKF9763X, Power=63mW, Tolerance=1%
R7 R11 R12: library part R0007-A.11, "RES CHIP 0402 1K 1% 1/16W", Case Code (Imperial)=0402, Case Code (Metric)=1005, Manufacturer=Vishay, Manufacturer 2=Panasonic, Manufacturer Part Number 2=ERJ-2RKF1001X, Power=63mW, Tolerance=1%
R8: library part R0028-A.11, "RES CHIP 0402 220K 1% 1/16W", Case Code (Imperial)=0402, Case Code (Metric)=1005, Manufacturer=Vishay, Manufacturer 2=Panasonic, Manufacturer Part Number 2=ERJ-2RKF2203X, Power=63mW, Tolerance=1%
R15: library part R0009-A.11, "RES CHIP 0402 22R 1% 1/16W", Case Code (Imperial)=0402, Case Code (Metric)=1005, Manufacturer=Yageo, Power=63mW, Tolerance=1%
SJ1 SJ2 SJ3 SJ5: library part UT0002-A.5, "Solder Jumper 0805 THIS IS NOT A COMPONENT"
SJ4: library part UT0006-A.12, "Solder Jumper shorted pads. This is not a component"
U1: library part M0001-A.8, "MODULE BLE 5.0 STAND ALONE nRF52", Manufacturer=UBlox
U2: library part U0217-A.3, "IC IMU 6 AXIS 14VFLGA pin to pin alternative to LSM6DSOXTR", Manufacturer="Bosch Sensortech"
U3: library part U0074-A.4, "SENS MEMS AUDIO OMNIDIRECTIONAL", Manufacturer=STMicroelectronics
U4: library part U0034-A.5, "IC AUTHENTICATION CHIP UDFN8", Manufacturer=Microchip
U5: library part U0136-A.7, "IC SENS OPT 560NM AMBIENT MODULE APDS-9960", Manufacturer=Broadcom
U6: library part U0072-A.5, "IC STEP DOWN CONV 1A 22V QFN8", Manufacturer="Monolithic Power Systems"
U7: library part U0153-A.3, "IC SENSOR 3-AXIS GEOMAGNETIC", Case/Package=SMD/SMT, Manufacturer="Bosch Sensortec", Max Operating Temperature=85°C, Max Supply Current=20mA, Min Operating Temperature=-40°C, Operating Supply Voltage=3.6V, Package Quantity=10000
U8: library part U0253-A.4, "IC PRESSURE AND TEMPERATURE SENSOR 6-LGA", Manufacturer=Renesas
U9: library part U0009-A.5, "SENSOR PRESSURE 3.77 PSI ~ 18.27 PSI (26 kPa ~ 126 kPa) Absolute 24 b 10-WFLGA", Manufacturer=STMicroelectronics

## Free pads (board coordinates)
  rrect50% 1.4x1.2 smd far side paste-8 mask+0.05: JTAG_PAD(42.403,3.336) JTAG_PAD(42.403,14.444)
  rrect50% 1.3x1 smd paste-8 mask+0.05: JTAG_PAD(42.503,3.236) JTAG_PAD(42.503,14.544)
  round 1.651 hole 1.651 unplated: MH(1.27,1.27) MH(1.27,16.51) MH(41.91,1.27) MH(41.91,16.51)
  rrect50% 2.3x1.8 smd far side paste-8 mask+0.05: USB_N(1.189,13.97) USB_P(1.189,6.35) USB_P(1.189,8.89) USB_P(1.189,11.43)

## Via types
v1: diameter 0.4, hole 0.2, TOP to BOTTOM, tented both sides, 193 vias

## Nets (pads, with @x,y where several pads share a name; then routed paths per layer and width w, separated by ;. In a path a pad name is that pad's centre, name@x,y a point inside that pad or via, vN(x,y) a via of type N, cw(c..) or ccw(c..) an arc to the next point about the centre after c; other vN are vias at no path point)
+3V3: C8.2 C9.1 C15.2 C17.2 C21.2 DL3.1 JP2.2 R3.2 R4.2 R5.2 R15.2 SJ4.2 TP_3V3.X U1.9 U1.10 U4.8 U5.5 | length 89.3
  TOP w0.15: v1(26.134,4.853) 26.134,5.181 26.764,5.81 R4.2@26.779,5.81
  TOP w0.2: R3.2@4.94,3.375 4.94,3.338 5.115,3.163 5.115,3.154 6.137,2.132 6.137,1.483 JP2.2@6.193,1.427 ; JP2.2@6.35,1.27 JP2.2@6.546,1.466 ; R5.2@11.575,13.04 C21.2@12.8,13.04 12.931,12.909 12.931,12.65 13.326,12.255 v1(13.326,10.791) ; 13.326,12.15 U4.8@13.87,12.15 ; R15.2@22.463,5.86 C15.2@23.534,5.86 ; C15.2@23.544,5.87 23.555,5.881 23.993,5.881 v1(24.004,5.892) 24.034,5.922 24.034,7.127 23.744,7.417 U5.5@23.744,8.19 23.744,8.65 v1(23.98,8.886) 24.034,8.886 24.134,8.986 24.153,8.986 24.38,9.213 24.38,10.583 24.38,11.384 25.141,12.145 26.215,12.145 DL3.1@26.255,12.105
  TOP w0.3: v1(12.55,7.725) 12.55,8.475 13.326,9.251 v1(13.326,10.791) ; C8.2@37.41,3.32 37.41,3.73 37.568,3.888 37.833,3.888 v1(37.852,3.907) U1.9@37.852,4.765 ; C9.1@38.34,3.32 38.34,3.685 38.552,3.897 v1(38.552,3.907) 38.571,3.926 38.676,3.926 38.852,4.102 U1.10@38.852,4.765
  TOP w0.4: C17.2@15.37,8.15 15.461,8.059 v1(15.937,8.059)
  SIG w0.45: v1@17.928,2.901 18.89,2.901 19.373,2.417 28.547,2.417 29.66,3.53 31.44,3.53 32.528,2.442 38,2.442 38.329,2.77 38.329,3.884 v1@38.352,3.907 ; v1(37.852,3.907) v1@38.352,3.907 ; v1(38.552,3.907) v1@38.352,3.907
  BOTTOM w0.3: v1(12.55,7.725) 12.577,7.725 12.677,7.625 13.617,7.625 14.052,8.059 v1(15.937,8.059) ; v1(13.326,10.791) 15.963,10.791 16.703,10.051 19.214,10.051 19.675,9.59 22.079,9.59 22.784,8.886 v1(23.98,8.886) ; 18.42,3.68 18.511,3.589 ; 18.511,3.289 18.611,3.389 ; v1(24.004,5.892) 24.004,5.865 24.276,5.593 25.719,5.593 26.115,5.197 26.115,4.872 v1(26.134,4.853) ; v1(37.852,3.907) 37.852,4.395 39.156,5.7 39.156,6.238 TP_3V3.X@39.268,6.35
  BOTTOM w0.5: JP2.2@6.35,1.27 6.598,1.27 7.888,2.56 17.609,2.56 17.902,2.853 v1(17.902,2.874) 18.096,2.874 18.511,3.289 18.511,3.589 18.511,4.689 17.17,6.03 SJ4.2@17.17,6.82 17.17,7.62 16.731,8.059 v1(15.937,8.059)
AIN0_A5/SCL: JP2.9 U1.18 | length 23.8
  TOP w0.15: U1.18@36.852,13.015 v1(36.852,14.149)
  BOTTOM w0.127: JP2.9@24.126,1.27 25.113,2.257 28.091,2.257 28.391,2.557 28.927,2.557 29.913,3.543 29.913,5.434 30.366,5.887 30.366,5.89 30.883,6.406 31.217,6.406 32.1,6.406 32.253,6.56 35.31,6.56 35.547,6.796 35.547,8.294 35.91,8.657 35.91,12.287 36.357,12.734 36.357,13.654 v1(36.852,14.149)
AIN1_A7: JP2.11 U1.16 | length 21.4
  TOP w0.15: v1(38.347,14.445) 38.852,13.94 U1.16@38.852,13.015
  BOTTOM w0.127: JP2.11@29.195,1.27 29.42,1.27 30.799,2.649 30.799,5.536 30.813,5.551 30.92,5.657 30.92,5.66 31.103,5.843 32.421,5.843 32.66,5.843 32.776,5.96 35.559,5.96 36.153,6.554 36.153,7.888 36.539,8.275 36.539,11.104 37.342,11.907 37.342,12.64 38.498,13.795 38.498,14.014 38.347,14.165 v1(38.347,14.445)
AIN2_A0: JP2.4 U1.25 | length 37.1
  TOP w0.15: v1(6.894,2.563) 7.578,3.248 7.578,3.821 v1(8.253,4.495) ; v1(9.134,6.917) 9.973,7.756 9.973,9.543 10.605,10.175 12.565,10.175 v1(12.6,10.14) ; v1(29.85,13.805) 29.85,13.017 U1.25@29.852,13.015
  SIG w0.15: v1(6.894,2.563) 6.905,2.575 7.601,2.575 7.768,2.408 9.492,2.408 9.949,1.951 10.734,1.951 JP2.4@11.415,1.27 ; v1(8.253,4.495) 8.253,6.078 9.092,6.917 v1(9.134,6.917)
  BOTTOM w0.15: v1(12.6,10.14) 12.6,10.84 12.985,11.225 15.716,11.225 15.995,11.504 16.656,11.504 16.66,11.5 17.565,11.5 18.398,12.333 19.484,13.418 21.032,13.418 21.759,12.691 23.796,12.691 25.224,14.119 29.162,14.119 29.476,13.805 v1(29.85,13.805)
AIN3_A1: JP2.5 U1.27 | length 34.6
  TOP w0.15: v1(8.376,3.312) 9.406,2.283 12.128,2.283 13.118,1.292 13.948,1.292 JP2.5@13.97,1.27 ; U1.27@29.927,9.89 30.096,10.06 v1(30.644,10.06)
  SIG w0.127: v1(8.376,3.312) 8.401,3.338 9.778,3.338 10.316,2.8 15.104,2.8 17.179,4.875 19.888,4.875 20.443,5.431 21.399,5.431 21.55,5.582 22.984,5.582 23.218,5.348 24.982,5.348 25.219,5.585 27.19,5.585 27.48,5.875 29.378,5.875 v1(29.675,6.173)
  BOTTOM w0.127: v1(29.675,6.173) 30.156,6.653 30.156,9.572 v1(30.644,10.06)
AIN4_A6: JP2.10 U1.17 | length 22.1
  TOP w0.15: U1.17@37.852,13.015 37.982,13.145 v1(37.982,13.928)
  BOTTOM w0.127: JP2.10@26.67,1.27 27.357,1.957 28.215,1.957 28.515,2.257 29.841,2.257 30.508,2.924 30.508,5.637 30.643,5.772 30.643,5.775 30.997,6.129 31.332,6.129 32.264,6.129 32.394,6.26 35.434,6.26 35.85,6.675 35.85,8.078 36.225,8.454 36.225,11.4 37.007,12.183 37.007,12.729 37.934,13.656 37.934,13.881 v1(37.982,13.928)
AIN5_A3: JP2.7 U1.23 | length 23.2
  TOP w0.15: v1(31.548,13.802) 31.594,13.756 31.594,13.273 U1.23@31.852,13.015
  BOTTOM w0.127: JP2.7@19.05,1.27 19.741,1.961 20.636,1.961 21.242,2.567 24.539,2.567 24.829,2.857 27.843,2.857 28.143,3.157 28.744,3.157 29.262,3.675 29.262,6.344 29.879,6.961 29.879,10.108 30.922,11.151 30.922,12.544 31.526,13.148 31.526,13.78 v1(31.548,13.802)
AIN6_A2: JP2.6 U1.24 | length 25.1
  TOP w0.15: v1(30.826,13.805) 30.826,13.04 U1.24@30.852,13.015
  BOTTOM w0.127: JP2.6@16.51,1.27 16.577,1.337 17.532,1.337 18.525,2.33 20.381,2.33 20.909,2.858 24.378,2.858 24.677,3.157 27.718,3.157 28.018,3.457 28.652,3.457 28.985,3.79 28.985,6.459 29.122,6.596 29.566,7.04 29.566,10.22 30.622,11.275 30.622,12.727 30.852,12.957 30.852,13.78 v1(30.826,13.805)
AIN7_A4/SDA: JP2.8 U1.20 | length 24.6
  TOP w0.15: U1.20@34.852,13.015 34.852,13.734 34.965,13.848 v1(34.965,13.915)
  BOTTOM w0.127: JP2.8@21.575,1.27 21.759,1.27 22.752,2.263 24.679,2.263 24.973,2.557 27.999,2.557 28.322,2.88 28.858,2.88 29.636,3.658 29.636,5.548 30.089,6.001 30.089,6.004 30.433,6.348 30.433,7.036 30.698,7.302 32.169,7.302 32.611,6.86 33.195,6.86 33.73,7.395 33.73,8.135 34.309,8.714 34.309,9.303 34.312,9.305 34.312,10.924 34.598,11.211 34.598,11.908 34.602,11.911 34.602,12.264 34.598,12.267 34.598,13.548 v1(34.965,13.915)
AREF: JP2.3
BMI270_INT1: U1.32 U2.4 | length 22
  TOP w0.15: v1(15.861,9.488) 15.867,9.488 16.127,9.228 16.127,8.472 16.309,8.29 16.377,8.29 16.477,8.19 16.752,8.19 U2.4@16.802,8.14 ; U1.32@32.402,6.14 32.402,6.705 32.745,7.049 32.745,7.345 v1(32.542,7.549)
  SIG w0.127: v1(15.861,9.488) 15.911,9.538 16.933,9.538 19.285,7.185 19.993,7.185 20.129,7.049 23.191,7.049 23.698,7.555 26.896,7.555 27.508,8.167 28.891,8.167 29.502,7.557 v1@32.542,7.557
BMI270_INT2: U1.50 U2.9 | length 12.2
  TOP w0.15: U2.9@19.752,8.64 19.767,8.654 20.131,8.654 v1(20.145,8.669)
  TOP w0.25: v1(27.981,9.974) 28.01,9.946 28.646,9.946 U1.50@28.702,9.89
  SIG w0.15: v1(20.145,8.669) 19.528,9.286 19.528,10.355 19.777,10.604 20.419,10.604 21.061,10.604 22.045,9.62 26.852,9.62 27.206,9.974 v1(27.981,9.974)
D2: JP3.5 U1.39 | length 8.4
  TOP w0.15: v1(34.177,12.088) 34.177,12.065 U1.39@34.602,11.64
  BOTTOM w0.15: JP3.5@29.195,16.51 30.182,15.523 32.327,15.523 34.206,13.644 34.206,12.116 v1(34.177,12.088)
D3~: JP3.6 U1.21 | length 9.9
  TOP w0.15: v1(33.446,15.514) 33.469,15.514 33.852,15.131 U1.21@33.852,13.015
  SIG w0.15: JP3.6@26.655,16.51 27.316,15.849 28.206,15.849 28.604,15.451 33.315,15.451 33.378,15.514 v1(33.446,15.514)
D4: JP3.7 U1.40 | length 12.7
  TOP w0.15: v1(33.352,12.149) 33.352,11.79 U1.40@33.502,11.64
  BOTTOM w0.15: JP3.7@24.115,16.51 24.192,16.51 25.37,15.332 29.646,15.332 29.811,15.168 32.258,15.168 33.352,14.074 v1(33.352,12.149)
D5~: JP3.8 U1.22 | length 13.4
  TOP w0.15: v1(32.816,13.841) 32.816,13.051 U1.22@32.852,13.015
  BOTTOM w0.15: JP3.8@21.575,16.51 22.442,15.643 23.586,15.643 24.197,15.032 29.522,15.032 29.686,14.868 32.133,14.868 32.816,14.185 v1(32.816,13.841)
